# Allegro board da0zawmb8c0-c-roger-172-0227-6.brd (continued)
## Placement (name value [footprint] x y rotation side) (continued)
R14  100_1%_2  [R0201]  105.47 71.87 90 top
R15  *51_5%_2  [R0201]  103.82 75.49 180 top
R16  49.9_1%_2  [R0201]  77.91 46.85 180 top
R17  *51_5%_2  [R0201]  103.59 70.12 180 top
R18  49.9_1%_2  [R0201]  83.93 47.36 180 top
R19  51_5%_2  [R0201]  102.09 72.33 270 top
R20  49.9_1%_2  [R0201]  101.15 76.29 0 bottom
R21  49.9_1%_2  [R0201]  101.15 75.53 180 bottom
R22  100_1%_2  [R0201]  106.46 70.55 90 top
R23  1K_5%_2  [R0201]  105.6 71.66 0 bottom
R24  51_5%_2  [R0201]  102.22 73.95 180 top
R25  *51_5%_2  [R0201]  105.27 69.96 270 top
R26  470_1%_4  [R0402]  50.73 33.64 270 top
R27  *Short_0402  [S0402]  49.72 32.88 270 top
R28  121_1%_4  [R0402]  81.77 48.53 180 top
R29  80.6_1%_4  [R0402]  82.26 47.56 0 top
R30  100_1%_4  [R0402]  77.91 48.63 0 top
R31  *10K_5%_4  [R0402]  66.74 29.07 180 bottom
R32  *10K_5%_4  [R0402]  64.2 40.63 180 top
R33  8.2K_5%_4  [R0402]  59.62 51.17 270 top
R34  *1K_5%_4  [R0402]  102.3 60.18 0 bottom
R35  10K_5%_4  [R0402]  64.45 39.33 90 bottom
R36  10K_5%_4  [R0402]  60.77 51.93 90 top
R37  8.2K_5%_4  [R0402]  64.96 37.98 0 bottom
R38  100K_1%_4  [R0402]  60.64 52.18 90 bottom
R39  *0_5%_4  [R0402]  66.74 30.03 0 bottom
R40  100K_1%_4  [R0402]  64.96 35.75 0 bottom
R41  100K_1%_4  [R0402]  62.47 29.35 270 top
R42  1M_5%_2  [R0201]  48.96 26.02 180 top
R43  10K_1%_2  [R0201]  92.59 31.48 270 bottom
R44  4.7K_5%_2  [R0201]  81.19 44.69 270 top
R45  10K_5%_4  [R0402]  64.7 41.9 0 bottom
R46  10K_5%_4  [R0402]  65.34 44.69 90 top
R47  *Short_0402  [S0402]  62.93 43.8 0 top
R51  *0_5%_4  [R0402]  64.32 44.69 90 top
R52  1K_5%_2  [R0201]  103.06 54.15 90 bottom
R54  60.4_1%_2  [R0201]  101.13 54.32 90 bottom
R56  100K_1%_4  [R0402]  64.58 50.89 180 bottom
R59  *10K_5%_4  [R0402]  63.69 27.67 180 top
R60  10K_5%_4  [R0402]  96.79 25.36 90 bottom
R63  56.2_1%_4  [R0402]  105.6 69.73 180 bottom
R64  220_1%_4  [R0402]  103.57 69.79 180 bottom
R65  *54.9/F_4  [R0402]  105.6 70.7 0 bottom
R66  *0_4/S  [S0402]  101.38 68.79 270 bottom
R67  100_1%_4  [R0402]  103.57 71.28 0 bottom
R68  *0_4/S  [S0402]  101.79 70.22 180 bottom
R69  *Short_0402  [S0402]  101.53 56.4 90 bottom
R70  *Short_0603  [S0603]  109.23 44.18 90 top
R71  *Short_0603  [S0603]  63.43 54.22 180 top
R72  100_1%_2  [R0201]  80.43 47.43 90 top
R73  HDMI_N@10K_5%_4  [R0402]  66.74 31 0 bottom
R74  100_1%_2  [R0201]  79.46 47.43 90 top
R77  *Short_0805  [S0805]  88.67 60.88 270 top
R78  *Short_0805  [S0805]  86.69 60.88 270 top
R79  *0.0002_5%_0805  [R0805]  84.57 66.75 90 top
R80  *Short_0805  [S0805]  84.72 60.88 270 top
R81  *0.0002_5%_0805  [R0805]  86.54 66.75 90 top
R82  49.9_1%_2  [R0201]  104.38 68.44 270 top
R83  *1K_5%_2  [R0201]  105.47 73.37 180 bottom
R84  *Short_0402  [S0402]  66.74 43.42 180 bottom
R85  *0_5%_4  [R0402]  101.03 77.2 0 bottom
R86  *1K_5%_2  [R0201]  101.15 73.65 0 bottom
R87  1K_5%_2  [R0201]  101.15 74.66 0 bottom
R88  *100K_1%_4  [R0402]  66.74 33.21 0 bottom
R89  4.7K_5%_2  [R0201]  64.96 37.02 180 bottom
R90  *20K_1%_2  [R0201]  66.74 37.37 180 bottom
R91  22_1%_4  [R0402]  62.93 52.06 0 bottom
R92  22_1%_4  [R0402]  65.97 46.09 0 top
R94  10K_1%_2  [R0201]  82.61 28.31 270 top
R95  2.2K_5%_2  [R0201]  97.31 28.82 0 top
R96  8.2K_5%_4  [R0402]  81.09 25.01 90 top
R97  2.2K_5%_2  [R0201]  95.82 28.85 180 top
R98  *10K_1%_2  [R0201]  82.74 27.93 180 bottom
R99  2.2K_5%_2  [R0201]  93.03 28 270 top
R100  10K_5%_4  [R0402]  81.09 27.04 90 top
R101  2.2K_5%_2  [R0201]  92.06 28 270 top
R102  10K_1%_2  [R0201]  82.74 28.69 180 bottom
R103  2.2K_5%_2  [R0201]  89.72 31.61 180 bottom
R104  2.2K_5%_2  [R0201]  88.71 31.61 0 bottom
R106  33.2_1%_4  [R0402]  161.68 27.7 90 top
R107  100K_1%_4  [R0402]  162.01 33.08 0 top
R108  33.2_1%_4  [R0402]  160.72 27.7 90 top
R109  33.2_1%_4  [R0402]  161.99 31.61 0 top
R110  33.2_1%_4  [R0402]  159.75 27.7 90 top
R111  33.2_1%_4  [R0402]  160.46 31.41 90 top
R112  100K_1%_4  [R0402]  158.43 30.72 270 top
R113  33.2_1%_4  [R0402]  159.45 31.41 90 top
R114  4.7K_5%_2  [R0201]  69.63 16.71 270 top
R115  4.7K_5%_2  [R0201]  67.24 19.29 0 top
R116  *20K_1%_2  [R0201]  66.74 36.28 180 bottom
R117  *4.7K_5%_2  [R0201]  61.94 47.87 180 top
R118  1K_5%_2  [R0201]  62.6 46.6 90 top
R119  4.7K_5%_2  [R0201]  89.04 27.65 270 bottom
R120  *4.7K_5%_2  [R0201]  77.66 22.85 0 top
R121  *20K_1%_2  [R0201]  88.83 28.87 0 bottom
R122  10K_5%_4  [R0402]  76.31 23.51 270 top
R123  *10K_5%_4  [R0402]  90.87 27.93 90 top
R124  *20K_1%_2  [R0201]  65.97 40.47 180 top
R125  20K_1%_2  [R0201]  88.94 34.5 135 top
R134  10K_5%_4  [R0402]  93.38 26.28 90 bottom
R136  113_1%_4  [R0402]  95.44 40.63 180 top
R137  1K_5%_2  [R0201]  96.79 37.4 0 top
R138  1K_5%_2  [R0201]  96.58 39.33 0 top
R139  100_1%_2  [R0201]  95.92 38.37 180 top
R144  4.7K_5%_2  [R0201]  78.04 27.67 270 bottom
R145  60.4_1%_2  [R0201]  101.66 30.59 0 bottom
R146  150_1%_2  [R0201]  75.32 22.77 90 top
R147  200_1%_2  [R0201]  90.28 35.98 90 top
R148  10K_5%_4  [R0402]  97.22 35.42 90 top
R152  100K_5%_4  [R0402]  65.44 39.33 90 bottom
R153  *100K_5%_4  [R0402]  98.82 28.43 90 top
R154  10K_5%_4  [R0402]  65.97 34.68 0 top
R155  10K_5%_4  [R0402]  65.97 36.61 0 top
R157  *20K_1%_2  [R0201]  67.14 38.7 180 bottom
R158  100K_5%_4  [R0402]  97.85 30.26 270 top
R159  10K_5%_4  [R0402]  65.97 37.58 0 top
R161  *0_5%_4  [R0402]  79.44 27.67 90 bottom
R166  33.2_1%_4  [R0402]  98.87 31.1 90 bottom
R167  1M_5%_4  [R0402]  99.38 29.75 180 bottom
R168  33.2_1%_4  [R0402]  99.83 31.1 90 bottom
R169  10M_5%_4  [R0402]  77.91 31.36 180 bottom
R179  10K_5%_4  [R0402]  78.24 25.39 90 top
R180  20K_1%_2  [R0201]  194.14 23.61 180 bottom
R183  *4.7K_5%_2  [R0201]  106.41 32.65 90 top
R186  *1K_5%_2  [R0201]  61.66 48.88 90 bottom
R187  33_5%_2  [R0201]  62.93 46.09 0 bottom
R188  33_5%_2  [R0201]  61.28 49.01 0 top
R191  33_5%_2  [R0201]  62.93 45.12 0 bottom
R194  33_5%_2  [R0201]  62.82 50.53 180 top
R202  20K_1%_2  [R0201]  95.82 25.64 270 bottom
R209  200_1%_2  [R0201]  71.05 33.01 180 bottom
R210  *Short_0402  [S0402]  66.61 24.88 90 top
R211  *Short_0402  [S0402]  82.31 30.52 180 bottom
R212  *0_5%_4  [R0402]  89.52 27.52 0 top
R213  *Short_0402  [S0402]  89.8 30.24 0 top
R215  *100K_5%_4  [R0402]  60.16 24.4 270 bottom
R216  *1K_5%_2  [R0201]  105.73 68.97 180 top
R217  *1K_5%_2  [R0201]  101.13 75.07 90 top
R218  1K_5%_2  [R0201]  105.7 67.97 180 top
R220  *1K_5%_2  [R0201]  113.6 20.69 90 top
R221  *1K_5%_2  [R0201]  114.06 22.9 0 top
R222  *1.5K_5%_4  [R0402]  114.06 23.91 0 top
R224  240_1%_2  [R0201]  49.85 62.47 90 top
R225  *0_5%_4  [R0402]  48.32 34.28 180 top
R226  *0_5%_4  [R0402]  46.8 31.1 180 top
R227  *0_5%_4  [R0402]  50.48 54.6 180 top
R228  *Short_0402  [S0402]  48.32 33.26 0 top
R229  *Short_0402  [S0402]  47.48 32.09 0 top
R230  *Short_0402  [S0402]  52.26 54.34 180 top
R231  240_1%_2  [R0201]  61.63 72.12 0 bottom
R232  240_1%_2  [R0201]  61.63 73.14 0 bottom
R233  240_1%_2  [R0201]  50.23 73.52 180 top
R234  240_1%_2  [R0201]  61.63 74.15 180 bottom
R235  240_1%_2  [R0201]  61.63 71.11 180 bottom
R236  240_1%_2  [R0201]  61.63 70.09 180 bottom
R237  240_1%_2  [R0201]  50.23 74.54 180 top
R238  240_1%_2  [R0201]  61.63 75.17 180 bottom
R239  240_1%_2  [R0201]  50.23 71.49 180 top
R240  240_1%_2  [R0201]  50.23 70.47 180 top
R241  1K_1%_4  [R0402]  50.35 50.41 0 top
R242  2_1%_6  [R0603]  50.1 48.6 270 top
R243  1K_1%_4  [R0402]  50.35 51.42 180 top
R244  24.9_1%_4  [R0402]  49.85 46.34 90 top
R245  *Short_0402  [S0402]  41.46 34.91 180 top
R246  *Short_0402  [S0402]  42.61 48.12 0 top
R247  *Short_0402  [S0402]  43.62 69.46 0 top
R248  *Short_0402  [S0402]  44.89 82.79 0 top
R252  *0_5%_4  [R0402]  30.16 40.5 180 top
R253  240_1%_4  [R0402]  39.69 34.91 0 top
R254  240_1%_4  [R0402]  40.83 48.12 0 top
R255  240_1%_4  [R0402]  41.84 69.46 0 top
R256  240_1%_4  [R0402]  42.99 82.79 0 top
R257  *Short_0402  [S0402]  30.16 39.33 180 top
R261  1.8K_1%_4  [R0402]  44.61 96.51 270 top
R262  2.7_5%_6  [R0603]  51.37 98.89 0 top
R263  *0_5%_4  [R0402]  49.46 99.3 90 top
R264  1.8K_1%_4  [R0402]  47.43 98.54 90 top
R265  33_5%_4  [R0402]  29.27 88.43 0 top
R266  33_5%_4  [R0402]  29.27 87.46 0 top
R267  24.9_1%_4  [R0402]  55.43 99.17 180 top
R268  36_1%_4  [R0402]  37.32 96.63 90 top
R269  36_1%_4  [R0402]  29.27 84.57 180 top
R270  36_1%_4  [R0402]  38.29 96.63 90 top
R271  51_1%_4  [R0402]  32.32 82.79 0 top
R272  36_1%_4  [R0402]  42.15 96.63 90 top
R273  36_1%_4  [R0402]  40.22 96.63 90 top
R274  36_1%_4  [R0402]  30.29 95.24 180 top
R275  36_1%_4  [R0402]  30.29 92.34 180 top
R276  36_1%_4  [R0402]  29.6 96.63 90 top
R277  36_1%_4  [R0402]  30.29 93.31 180 top
R278  36_1%_4  [R0402]  30.29 90.41 180 top
R279  36_1%_4  [R0402]  30.29 94.27 180 top
R280  36_1%_4  [R0402]  34.43 96.63 90 top
R281  36_1%_4  [R0402]  29.27 86.5 180 top
R282  36_1%_4  [R0402]  33.46 96.63 90 top
R283  36_1%_4  [R0402]  30.29 91.38 180 top
R284  36_1%_4  [R0402]  39.25 96.63 90 top
R285  36_1%_4  [R0402]  31.53 96.63 90 top
R286  36_1%_4  [R0402]  35.39 96.63 90 top
R287  36_1%_4  [R0402]  30.29 89.44 180 top
R288  36_1%_4  [R0402]  36.36 96.63 90 top
R289  36_1%_4  [R0402]  29.27 85.53 180 top
R290  36_1%_4  [R0402]  32.5 96.63 90 top
R291  36_1%_4  [R0402]  41.18 96.63 90 top
R292  36_1%_4  [R0402]  43.11 96.63 90 top
R293  36_1%_4  [R0402]  30.57 96.63 90 top
R294  *36_1%_4  [R0402]  30.16 41.64 0 top
R296  *short_4  [S0402]  102.42 125.34 0 bottom
R297  EV@10K_1%_4  [R0402]  85.13 95.77 270 bottom
R299  *EV@Short_0402  [S0402]  101.28 109.33 180 top
R305  *EV@Short_0402  [S0402]  100.26 123.3 0 bottom
R306  EV@100K_1%_4  [R0402]  100.26 124.32 180 bottom
R307  *EV@200_1%_2  [R0201]  115.25 117.84 180 bottom
R311  EV@10K_1%_4  [R0402]  103.34 117.82 180 bottom
R312  EV@2.49K_1%_4  [R0402]  116.65 118.22 90 bottom
R313  EV@10K_1%_4  [R0402]  90.49 98.16 0 bottom
R314  EV@10K_1%_4  [R0402]  119.19 100.44 270 bottom
R315  EV@10K_1%_4  [R0402]  119.57 99.05 0 bottom
R316  EV@10K_1%_4  [R0402]  120.33 98.03 0 bottom
R317  EV@10K_1%_4  [R0402]  120.2 104.63 0 top
R318  EV@40.2_1%_4  [R0402]  120.2 93.08 0 top
R319  EV@40.2_1%_4  [R0402]  120.2 94.09 0 top
R320  EV@60.4_1%_2  [R0201]  120.48 94.09 0 bottom
R321  *EV@60.4_1%_2  [R0201]  110.43 97.11 0 top
R322  *EV@60.4_1%_2  [R0201]  110.76 100.01 270 top
R323  *EV@0_5%_4  [R0402]  100.77 118.22 180 bottom
R324  *EV@Short_0402  [S0402]  100.77 119.24 180 bottom
R325  EV@100K_1%_4  [R0402]  102.75 123.81 90 bottom
R326  EV@10K_5%_4  [R0402]  91.6 89.01 90 bottom
R329  *EV@Short_0402  [S0402]  98.63 102.8 90 top
R330  *EV@10K_1%_4  [R0402]  97.39 89.01 90 bottom
R331  EV@10K_1%_4  [R0402]  97.85 87.36 0 bottom
R332  EV@10K_1%_4  [R0402]  98.36 89.01 90 bottom
R339  *EV@Short_0402  [S0402]  108.98 88.81 180 bottom
R340  10K_1%_2  [R0201]  201.86 15.78 0 top
R341  EV@100K_5%_4  [R0402]  105.47 88.81 180 bottom
R342  EV@100K_5%_4  [R0402]  103.69 88.81 0 bottom
R343  EV@100K_5%_4  [R0402]  107.25 88.81 180 bottom
R344  EV@100K_5%_4  [R0402]  88.2 96.63 0 bottom
R345  EV@100K_5%_4  [R0402]  88.2 95.62 0 bottom
R346  EV@100K_5%_4  [R0402]  88.2 93.59 0 bottom
R347  *EV@100K_5%_4  [R0402]  88.2 97.65 0 bottom
R348  *EV@100K_5%_4  [R0402]  88.2 92.57 0 bottom
R349  *EV@100K_5%_4  [R0402]  88.2 94.6 0 bottom
R350  *EV@30.1K_1%_4  [R0402]  105.47 89.78 0 bottom
R351  *EV@100K_5%_4  [R0402]  107.25 89.78 180 bottom
R352  EV@100K_5%_4  [R0402]  103.69 89.78 180 bottom
R353  EV@100K_5%_4  [R0402]  90.49 96.13 180 bottom
R354  EV@100K_5%_4  [R0402]  90.49 94.98 0 bottom
R355  EV@100K_5%_4  [R0402]  90.49 92.95 180 bottom
R356  EV@100K_5%_4  [R0402]  90.49 97.14 180 bottom
R357  EV@100K_5%_4  [R0402]  90.49 91.93 180 bottom
R358  EV@100K_5%_4  [R0402]  90.49 93.97 180 bottom
R359  *0_5%_4  [R0402]  179.08 31.91 90 top
R361  4.7K_5%_2  [R0201]  192.82 32.24 90 top
R362  EV@4.7K_5%_2  [R0201]  171.36 30.19 0 top
R363  EV@2.2K_5%_2  [R0201]  96.43 89.01 270 bottom
R364  *EV@Short_0402  [S0402]  96.12 87.36 0 bottom
R365  EV@4.7K_5%_2  [R0201]  173.11 30.19 180 top
R366  EV@2.2K_5%_2  [R0201]  95.46 89.01 270 bottom
R367  EV@2.2K_5%_2  [R0201]  94.5 89.01 270 bottom
R368  EV@2.2K_5%_2  [R0201]  93.53 89.01 270 bottom
R369  4.7K_5%_2  [R0201]  192.11 32.24 90 top
R370  *EV@Short_0402  [S0402]  90.23 89.95 180 bottom
R372  *EV@Short_0402  [S0402]  90.18 95.01 270 top
R373  *EV@Short_0402  [S0402]  89.85 98.67 180 top
R374  *EV@Short_0402  [S0402]  87.95 97.01 180 top
R376  *EV@Short_0402  [S0402]  90.23 90.92 180 bottom
R378  *EV@10K_1%_4  [R0402]  202.37 12.94 180 top
R380  43_5%_4  [R0402]  179.08 30.19 270 top
R382  *EV@0_5%_4  [R0402]  100.52 124.07 180 top
R383  4.7K_5%_2  [R0201]  190.69 32.27 90 top
R384  *EV@Short_0402  [S0402]  102.3 124.07 180 top
R385  *EV@4.7K_5%_2  [R0201]  100.52 123.05 0 top
R386  EV@10K_5%_4  [R0402]  85.79 94.73 270 top
R391  EV@10K_1%_4  [R0402]  87.95 90.56 0 bottom
R394  EV@10K_1%_4  [R0402]  90.18 93.1 90 top
R395  EV@10K_1%_4  [R0402]  90.23 88.99 0 bottom
R396  EV@10K_1%_4  [R0402]  95.06 119.24 180 bottom
R397  EV@10K_1%_4  [R0402]  87.95 98.03 0 top
R398  EV@100K_1%_4  [R0402]  98.74 96.63 90 top
R399  *EV@10K_1%_4  [R0402]  88.2 89.52 0 bottom
R402  *22_5%_4  [R0402]  179.87 23.23 180 top
R403  EV@10K_1%_4  [R0402]  85.41 97.01 0 top
R404  EV@10K_1%_4  [R0402]  88.2 91.55 0 bottom
R405  EV@120_1%_4  [R0402]  132.78 97.65 90 bottom
R406  EV@120_1%_4  [R0402]  132.4 102.35 180 bottom
R407  EV@549_1%_4  [R0402]  133.92 100.06 0 top
R409  100K_1%_4  [R0402]  53.78 26.4 90 top
R410  EV@1.33K_1%_4  [R0402]  133.92 99.05 0 top
R411  EV@931_1%_4  [R0402]  133.92 101.08 0 top
R414  TPC@20K_1%_2  [R0201]  16.7 47.23 90 top
R415  TPC@39K_1%_4  [R0402]  16.7 49.01 90 top
R416  TPC@100K_5%_4  [R0402]  23.56 47.36 90 top
R417  TPC@10K_5%_4  [R0402]  23.94 49.9 0 top
R418  TPC@10K_5%_4  [R0402]  23.94 48.88 0 top
R421  *Short_0402  [S0402]  22.69 53.45 180 top
R422  *Short_0402  [S0402]  22.69 54.47 180 top
R423  *Short_0402  [S0402]  23.94 58.66 180 top
R424  *Short_0402  [S0402]  23.94 57.64 180 top
R425  *Short_0402  [S0402]  22.16 34.15 180 top
R426  *Short_0402  [S0402]  22.16 35.17 180 top
R427  *Short_0402  [S0402]  22.16 32.12 180 top
R428  *Short_0402  [S0402]  22.16 33.13 180 top
R429  *Short_0402  [S0402]  22.67 36.94 180 top
R430  *Short_0402  [S0402]  22.67 37.96 180 top
R436  *short_4  [S0402]  56.45 104.89 180 top
R439  *1K_5%_2  [R0201]  52.36 107.3 270 top
R440  *1K_5%_2  [R0201]  59.02 110.73 270 top
R441  1K_1%_4  [R0402]  54.29 107.3 90 top
R442  100K_1%_4  [R0402]  55.26 107.3 270 top
R443  10_5%_4  [R0402]  53.33 107.3 270 top
R445  *short_4  [S0402]  82.61 96.02 180 bottom
R446  100K_1%_4  [R0402]  80.83 96.02 180 bottom
R447  100K_5%_4  [R0402]  203.16 38.37 90 bottom
R448  256@0_5%_4  [R0402]  213.12 32.29 0 top
R449  255@0_5%_4  [R0402]  211.72 36.18 90 bottom
R450  *short_6  [S0603]  198.49 34.73 0 bottom
R451  200K_1%_4  [R0402]  199.43 30.72 0 bottom
R452  255@100K_5%_4  [R0402]  200.59 29.04 90 bottom
R453  *256@0_5%_4  [R0402]  208.67 30.24 90 top
R454  *255@0_5%_4  [R0402]  209.31 28.21 270 top
R455  *Short_0603  [S0603]  211.15 25.34 0 bottom
R459  *Short_0402  [S0402]  208.01 28.13 90 bottom
R460  *short_4  [S0402]  204.84 27.52 90 top
R461  22_5%_2  [R0201]  206.74 27.57 90 bottom
R462  *0_5%_4  [R0402]  202.63 27.52 90 top
R463  *short_4  [S0402]  210.63 37.83 180 top
R464  *0_5%_4  [R0402]  210.75 35.8 180 top
R465  *0_5%_4  [R0402]  198.03 29.7 90 bottom
R467  *0_5%_4  [R0402]  198.77 35.95 0 bottom
R468  2.2K_5%_2  [R0201]  213.57 42.91 0 top
R469  *0_5%_4  [R0402]  210.63 38.85 180 top
R470  *short_4  [S0402]  202.02 29.83 135 top
R471  2.2K_5%_2  [R0201]  213.57 43.93 0 top
R472  62_1%_4  [R0402]  213.55 46.62 0 top
R473  62_1%_4  [R0402]  213.55 47.66 0 top
R474  *10K_5%_4  [R0402]  215.38 45.22 180 top
R475  *10K_5%_4  [R0402]  214.82 49.01 180 top
R476  4.7K_5%_2  [R0201]  213.57 45.27 90 top
R477  4.7K_5%_2  [R0201]  213.09 48.63 0 top
R478  1K_5%_2  [R0201]  210.65 28.28 0 top
R479  *10K_5%_4  [R0402]  210.65 29.3 180 top
R480  *Short_0603  [S0603]  118.86 17.97 270 top
R481  *Short_0603  [S0603]  117.44 17.97 270 top
R482  *Short_0603  [S0603]  116.01 17.97 270 top
R483  *Short_0603  [S0603]  114.54 17.97 270 top
R484  *150_1%_4  [R0402]  14.16 78.73 90 bottom
R486  *150_1%_4  [R0402]  14.16 76.82 90 bottom
R487  *150_1%_4  [R0402]  14.16 74.92 90 bottom
R489  *150_1%_4  [R0402]  14.16 80.76 90 bottom
R490  2.2K_5%_2  [R0201]  20.25 74.15 90 top
R491  2.2K_5%_2  [R0201]  22.24 73.65 90 top
R494  2.2K_5%_2  [R0201]  18.73 83.64 270 top
R495  *HDD_R@4.7K_5%_2  [R0201]  204.53 14.74 180 top
R497  HDD_R@4.7K_5%_2  [R0201]  206.82 13.32 0 top
R498  *HDD_R@4.7K_5%_2  [R0201]  204.53 13.78 180 top
R499  *HDD_R@4.7K_5%_2  [R0201]  206.82 12.56 0 top
R500  HDD_R@4.7K_5%_2  [R0201]  204.53 12.81 180 top
R502  2.2K_5%_2  [R0201]  19.75 83.64 270 top
R503  *HDD_R@4.7K_5%_2  [R0201]  204.53 15.71 180 top
R504  HDD_R@4.7K_5%_2  [R0201]  206.82 16.75 0 top
R505  *HDD_R@4.7K_5%_2  [R0201]  204.53 16.67 180 top
R506  *HDD_R@4.7K_5%_2  [R0201]  206.82 18.91 0 top
R507  HDMI_R@12.4K_1%_4  [R0402]  20.89 83.81 270 top
R508  2.49K_1%_4  [R0402]  42.18 112.36 90 top
R509  1K_5%_2  [R0201]  51.37 104.51 0 top
R510  15K_1%_4  [R0402]  49.59 104.61 0 top
R511  10_5%_4  [R0402]  45.78 109.84 90 top
R512  680_5%_4  [R0402]  44.77 109.84 270 top
R513  *short_4  [S0402]  49.59 105.57 0 top
R516  75_1%_8  [R0805]  37.53 111.37 90 top
R517  75_1%_8  [R0805]  34.73 111.37 90 top
R518  75_1%_8  [R0805]  31.68 111.62 90 top
R519  75_1%_8  [R0805]  28.76 111.52 90 top
R551  *10K_1%_2  [R0201]  94.22 25.87 270 bottom
R554  *10K_5%_4  [R0402]  93.86 29.81 270 bottom
R557  *0_5%_4  [R0402]  75.93 17.64 270 top
R558  *Short_0402  [S0402]  74.97 17.64 90 top
R559  4.7K_5%_2  [R0201]  69.18 21.32 270 top
R560  *Short_0402  [S0402]  70.65 19.44 180 top
R561  *0_5%_4  [R0402]  70.65 18.48 0 top
R562  4.7K_5%_2  [R0201]  73.34 18.4 0 top
R563  *10K_5%_4  [R0402]  70.55 20.74 0 top
R565  *10K_5%_4  [R0402]  76.13 19.29 0 top
R566  4.7K_5%_2  [R0201]  68.21 21.37 90 top
R567  4.7K_5%_2  [R0201]  73.72 20.43 180 top
R572  *short_4  [S0402]  76.54 23.91 180 bottom
R573  *short_4  [S0402]  78.29 21.47 90 top
R574  *10K_5%_4  [R0402]  78.42 22.97 180 bottom
R575  *Short_0805  [S0805]  176.34 27.24 180 top
R576  1K_5%_2  [R0201]  172.88 28.51 180 top
R579  KBL@10K_5%_4  [R0402]  196.12 18.96 270 bottom
R580  TPM@10K_1%_2  [R0201]  121.47 24.34 0 top
R582  *GS@Short_0402  [S0402]  54.04 24.5 90 top
R583  TPM@10K_1%_2  [R0201]  121.42 17.66 0 top
R586  TPM@10K_1%_2  [R0201]  121.25 22.11 0 top
R589  *short_4  [S0402]  63.69 22.24 0 top
R590  *GS@Short_0201  [S0201]  63.31 19.72 180 top
R591  *GS@Short_0201  [S0201]  60.39 17.39 90 top
R592  *TPM@Short_0201  [S0201]  125.69 16.27 0 top
R593  *TPM@Short_0201  [S0201]  121.47 23.61 0 top
R596  TPM@33_5%_2  [R0201]  120.41 23.61 0 top
R597  TPM@33_5%_2  [R0201]  121.7 20.65 0 top
R598  TPM@33_5%_2  [R0201]  121.42 16.95 0 top
R599  *TPM@Short_0201  [S0201]  121.19 22.85 0 top
R600  *TPM@1.2K_5%_2  [R0201]  130.34 20.56 180 top
R601  *TPM@Short_0201  [S0201]  122.87 24.5 270 top
R604  *49.9K_1%_2  [R0201]  90.03 26 90 bottom
R605  *49.9K_1%_4  [R0402]  91.35 29.78 270 bottom
R606  *49.9K_1%_4  [R0402]  91.68 28.03 90 bottom
R607  *49.9K_1%_2  [R0201]  91.37 31.48 270 bottom
R608  *PBA@0_5%_4  [R0402]  47.81 18.4 90 top
R609  PBA@10K_5%_4  [R0402]  52.64 18.27 270 top
R614  *short_4  [S0402]  55.31 21.83 180 bottom
R638  ODD@10K_5%_4  [R0402]  127.05 16.29 0 top
R639  *ODD@Short_0805  [S0805]  123.3 20.05 180 bottom
R640  ODD@33_5%_2  [R0201]  140.52 19.93 270 bottom
R641  *ODD@10K_5%_4  [R0402]  139.51 20.69 270 bottom
R645  *SSD@Short_0201  [S0201]  31.43 3.54 0 top
R646  *SSD@Short_0201  [S0201]  29.14 11.54 270 bottom
R647  *SSD@Short_0201  [S0201]  29.91 11.54 270 bottom
R648  *SSD@Short_0201  [S0201]  28.76 3.54 0 top
R649  SSD@100K_1%_4  [R0402]  22.29 8.24 180 top
R651  4.7K_5%_2  [R0201]  180.2 14.97 270 bottom
R652  4.7K_5%_2  [R0201]  181.37 19.85 270 bottom
R653  *SSD@Short_0201  [S0201]  26.73 6.59 180 top
R654  *SSD@0_5%_2  [R0201]  22.29 9.26 0 top
R655  *0_5%_4  [R0402]  195.06 17.89 270 bottom
R662  CNV@20K_1%_2  [R0201]  104.46 32.12 90 top
R663  CNV@20K_1%_2  [R0201]  105.22 32.12 90 top
R664  CNV@20K_1%_2  [R0201]  196.86 22.97 0 bottom
R665  CNV@22_1%_4  [R0402]  196.3 26.73 180 bottom
R666  CNV@33_5%_2  [R0201]  104.56 33.18 270 top
R667  CNV@22_1%_4  [R0402]  193.15 23.33 270 bottom
R668  CNV@33_5%_2  [R0201]  103.85 33.18 270 top
R670  *Short_0402  [S0402]  193.53 21.42 180 bottom
R671  *10K_1%_2  [R0201]  192.72 18.88 0 bottom
R672  *10K_1%_2  [R0201]  193.48 18.15 0 bottom
R673  *Debug@Short_0201  [S0201]  193.08 17.39 0 bottom
R674  *Debug@Short_0201  [S0201]  193.48 15.1 0 bottom
R675  *Debug@Short_0201  [S0201]  193.48 14.34 0 bottom
R676  CNV@75K_1%_4  [R0402]  146.87 29.7 180 top
R677  CNV@75K_1%_4  [R0402]  147.03 24.93 180 top
R678  CNV@75K_1%_4  [R0402]  147.84 23.63 0 top
R679  CNV@71.5K_1%_4  [R0402]  145.6 18.2 180 top
R696  *HDMI_R@Short_0201  [S0201]  15.56 74.26 180 top
R697  *HDMI_R@Short_0201  [S0201]  15.56 75.45 180 top
R698  *HDMI_R@Short_0201  [S0201]  15.56 76.16 180 top
R699  *HDMI_R@Short_0201  [S0201]  15.56 77.35 180 top
R700  *HDMI_R@Short_0201  [S0201]  15.56 78.07 180 top
R701  *HDMI_R@Short_0201  [S0201]  15.56 79.26 180 top
R702  *HDMI_R@Short_0201  [S0201]  15.56 79.97 180 top
R703  *HDMI_R@Short_0201  [S0201]  15.56 81.16 180 top
R706  HDMI_N@470_1%_4  [R0402]  13.78 81.39 0 top
R707  HDMI_N@470_1%_4  [R0402]  13.78 80.38 0 top
R708  HDMI_N@470_1%_4  [R0402]  13.78 79.36 0 top
R709  HDMI_N@470_1%_4  [R0402]  13.78 78.35 0 top
R710  HDMI_N@470_1%_4  [R0402]  13.78 77.33 0 top
R711  HDMI_N@470_1%_4  [R0402]  13.78 76.31 0 top
R712  HDMI_N@470_1%_4  [R0402]  13.78 75.3 0 top
R713  HDMI_N@470_1%_4  [R0402]  13.78 74.28 0 top
R720  33_5%_2  [R0201]  148.88 19.95 90 top
R732  *100K_5%_4  [R0402]  205.78 27.55 90 bottom
R733  256@100K_5%_4  [R0402]  200.16 29.4 180 top
R734  10K_1%_2  [R0201]  195.87 30.01 90 bottom
R735  *Short_0201  [S0201]  196.02 34.02 0 bottom
R736  255@0_5%_4  [R0402]  196.3 35.01 0 bottom
R737  256@0_5%_4  [R0402]  197.04 35.98 0 bottom
R738  255@0_5%_4  [R0402]  198.64 24.73 90 bottom
R739  256@0_5%_4  [R0402]  201.26 27.27 90 bottom
R740  256@0_5%_4  [R0402]  198.74 28.08 0 bottom
R741  256@3.3K_5%_2  [R0201]  198.64 26.1 180 bottom
R742  256@3.3K_5%_2  [R0201]  198.44 27.16 180 bottom
R746  *10K_5%_4  [R0402]  17.71 83.81 270 top
R747  10K_5%_4  [R0402]  23.05 84.31 90 top
R748  *0_5%_4  [R0402]  21.91 83.81 270 top
R749  0_5%_4  [R0402]  16.7 83.81 270 top
R750  *Short_0402  [S0402]  20 85.33 0 top
R775  *short_4  [S0402]  25.97 62.72 90 top
R777  *short_4  [S0402]  25.97 64.5 270 top
R821  1K/F_4  [R0402]  140.9 35.67 0 top
R822  1K/F_4  [R0402]  143.17 33.74 90 top
R825  *100K_1%_4  [R0402]  138.24 33.59 180 top
R890  100K_5%_2  [R0201]  180 16.42 270 top
R894  *Short_0201  [S0201]  179.21 18.27 0 top
R895  33_5%_2  [R0201]  196.25 32.24 90 top
R951  45.3K_1%_4  [R0402]  44.64 23.35 0 top
R953  1K/F_4  [R0402]  47.18 23 270 top
R956  33_5%_2  [R0201]  203.03 22.69 270 top
R960  33_5%_2  [R0201]  203.82 23.91 0 top
R971  20K_1%_2  [R0201]  48.96 27.04 0 top
R978  1.5K_5%_4  [R0402]  46.04 22.97 270 top
R979  20K_1%_2  [R0201]  48.96 25.01 0 top
R1234  HDD_R@4.7K_5%_2  [R0201]  206.82 14.72 0 top
R1235  HDD_R@4.7K_5%_2  [R0201]  206.82 15.61 0 top
R1236  *HDD_R@4.7K_5%_2  [R0201]  206.82 17.77 0 top
R1237  HDD_R@4.7K_5%_2  [R0201]  205.04 18.91 180 top
R1238  HDD_R@4.7K_5%_2  [R0201]  204.53 17.64 180 top
R1239  *HDD_R@Short_0402  [S0402]  204.91 11.16 90 top
R1250  20K_1%_2  [R0201]  15.09 86.98 0 top
R1251  *Short_0805  [S0805]  86.45 26.68 270 bottom
R1252  *20K_1%_2  [R0201]  80.83 27.42 270 bottom
R1253  *Short_0603  [S0603]  96.96 30.31 0 bottom
R1260  *Short_0402  [S0402]  100.01 35.04 180 top
R1262  *Short_0402  [S0402]  101.1 40.83 180 bottom
R1264  *Short_0402  [S0402]  101.38 39.86 180 bottom
R1265  *Short_0402  [S0402]  102.55 44.18 0 top
R1266  *Short_0402  [S0402]  102.55 42.25 0 top
R1267  *Short_0402  [S0402]  100.26 28.43 180 top
R1270  *Short_0402  [S0402]  86.04 31.1 90 top
R1271  *Short_0402  [S0402]  102.55 43.22 0 top
R1272  *Short_0603  [S0603]  96.96 28.74 180 bottom
R1273  *Short_0402  [S0402]  87.44 30.09 180 bottom
R1274  *Short_0402  [S0402]  87.44 28.79 180 bottom
R1275  *Short_0805  [S0805]  102.09 38.39 0 bottom
R1276  *Short_0402  [S0402]  87.06 31.1 270 top
R1277  *Short_0603  [S0603]  104.84 29.2 0 bottom
R1278  *Short_0402  [S0402]  88.83 32.56 0 top
R1279  *Short_0402  [S0402]  103.21 35.98 270 top
R1280  *Short_0402  [S0402]  100.65 44.49 0 top
R1281  *Short_0402  [S0402]  85.02 31.1 270 top
R1284  HDMI_N@0_5%_2  [R0201]  26.22 74.92 0 top
R1285  HDMI_N@0_5%_2  [R0201]  26.22 76.06 0 top
R1286  HDMI_N@0_5%_2  [R0201]  26.22 76.82 0 top
R1287  HDMI_N@0_5%_2  [R0201]  26.22 77.96 0 top
R1288  HDMI_N@0_5%_2  [R0201]  26.22 78.73 0 top
R1289  HDMI_N@0_5%_2  [R0201]  26.22 79.87 0 top
R1290  HDMI_N@0_5%_2  [R0201]  26.22 80.63 0 top
R1291  HDMI_N@0_5%_2  [R0201]  26.22 81.77 0 top
R2356  *Short_0201  [S0201]  200.77 21.96 0 top
R2525  *Short_0805  [S0805]  102.09 36.41 0 bottom
R2652  *SSD@Short_0201  [S0201]  39.05 11.54 270 bottom
R2653  *SSD@Short_0201  [S0201]  38.29 11.54 270 bottom
R2654  *SSD@Short_0201  [S0201]  35.75 11.54 270 bottom
R2655  *SSD@Short_0201  [S0201]  34.99 11.54 270 bottom
R2656  *SSD@Short_0201  [S0201]  32.95 11.54 270 bottom
R2657  *SSD@Short_0201  [S0201]  32.19 11.54 270 bottom
R2658  *SSD@Short_0201  [S0201]  27.75 11.54 270 bottom
R2659  *SSD@Short_0201  [S0201]  26.99 11.54 270 bottom
R2660  *SSD@100K_5%_4  [R0402]  31.43 2.65 180 top
R2661  *SSD@Short_0805  [S0805]  24.95 3.03 180 top
R2662  *Debug@Short_0201  [S0201]  193.48 13.58 0 bottom
R2663  *Debug@Short_0201  [S0201]  179.64 24.09 90 bottom
R2664  *Debug@Short_0201  [S0201]  181.37 24.88 90 bottom
R2665  *Short_0201  [S0201]  178.32 18.6 270 top
R2666  *CNV_N@0_5%_8  [R0805]  193.89 28.87 180 bottom
R2667  *CNV@Short_0805  [S0805]  193.76 26.48 180 bottom
R6504  TPC@100K_1%_4  [R0402]  27.75 18.02 90 bottom
R6505  TPC@100K_1%_4  [R0402]  27.52 19.8 90 bottom
R6506  *TPC@100K_1%_4  [R0402]  26.55 19.8 90 bottom
R6508  TPC@100K_1%_4  [R0402]  22.16 19.01 180 bottom
R6510  TPC@100K_1%_4  [R0402]  21.7 17.72 180 bottom
R6515  TPC@100K_1%_4  [R0402]  25.97 11.9 270 bottom
R6516  TPC@100K_1%_4  [R0402]  24.95 11.9 270 bottom
R6517  TPC@100K_1%_4  [R0402]  23.28 12.13 90 bottom
R6603  TPC@10K_1%_4  [R0402]  21.32 17.69 270 top
R9041  *TPC@4.7K_5%_4  [R0402]  25.16 20.18 90 bottom
R9042  TPC@4.7K_5%_4  [R0402]  24.19 20.18 90 bottom
R9048  *TPC@Short_0603  [S0603]  20.99 26.05 90 bottom
R9261  *Short_0805  [S0805]  111.67 45.1 0 top
R10880  *10K_1%_2  [R0201]  95.06 26.4 270 bottom
R25270  *100K_1%_4  [R0402]  60.72 108.06 0 top
R25271  *100K_1%_4  [R0402]  60.72 109.33 0 top
R25272  *TPC@4.7K_5%_2  [R0201]  20.13 24.24 180 bottom
R25273  *TPC@4.7K_5%_2  [R0201]  16.95 18.66 180 bottom
R25274  *TPC@4.7K_5%_2  [R0201]  19.75 25.64 90 bottom
R25275  *TPC@4.7K_5%_2  [R0201]  16.34 25.79 270 bottom
R25276  *TPC@4.7K_5%_2  [R0201]  19.32 18.4 270 bottom
R25277  *TPC@4.7K_5%_2  [R0201]  20.33 18.4 90 bottom
R25278  TPC@4.7K_5%_2  [R0201]  15.58 25.26 90 bottom
R25279  *TPC@4.7K_5%_2  [R0201]  16.95 19.67 0 bottom
R25280  *short_4  [S0402]  19.75 19.8 0 bottom
R25282  EV@1.33K_1%_4  [R0402]  132.65 104.38 180 top
R25283  EV@931_1%_4  [R0402]  134.43 103.11 0 top
R25284  EV@549_1%_4  [R0402]  134.43 104.38 0 top
R25285  *Short_0805  [S0805]  67.55 107.05 90 bottom
R25288  *Short_0402  [S0402]  46.16 103.62 90 bottom
R25289  *Short_0402  [S0402]  47.18 103.62 90 bottom
R25290  *Short_0402  [S0402]  44.13 103.62 90 bottom
R25291  *Short_0402  [S0402]  45.15 103.62 90 bottom
R25292  *TPC@Short_0402  [S0402]  11.49 11.8 180 top
R25293  *TPC@Short_0402  [S0402]  11.49 10.78 180 top
R25294  HDMI_N@1M_5%_2  [R0201]  18.1 85.33 180 top
R25295  *Short_0402  [S0402]  47.69 21.32 180 top
R25296  *Short_0805  [S0805]  49.21 111.75 270 top
R25297  *Short_0402  [S0402]  14.92 84.95 0 top
R25298  100K_5%_4  [R0402]  177.48 19.14 90 top
R25300  100K_5%_4  [R0402]  177.05 22.08 90 top
R25303  *10K_1%_2  [R0201]  194.96 32.24 90 top
R25304  4.7K_5%_2  [R0201]  189.98 32.27 90 top
R25306  2.2_5%_6  [R0603]  175.22 23.23 0 top
R25307  *2.2_5%_6  [R0603]  179.44 26.81 180 top
R25308  33_5%_2  [R0201]  183.91 32.35 180 top
R25309  10K_1%_2  [R0201]  195.64 31.36 180 top
R25310  100K_5%_4  [R0402]  65.21 102.98 90 top
R25311  100K_5%_2  [R0201]  201.99 17.05 0 top
R25312  10K_5%_4  [R0402]  171.11 28.31 180 top
R25314  10K_1%_2  [R0201]  193.53 32.24 90 top
R25315  33_5%_2  [R0201]  180.43 27.88 180 top
R25316  *10K_1%_2  [R0201]  194.24 32.24 90 top
R25317  2.2_5%_6  [R0603]  177.96 25.39 180 top
R25318  33_5%_2  [R0201]  197.52 11.62 180 top
R25320  100K_5%_2  [R0201]  181.72 30.21 270 top
R25321  *Short_0402  [S0402]  19.62 57.26 180 bottom
R25322  EV@10K_1%_4  [R0402]  200.47 12.94 180 top
R25323  *10K_1%_2  [R0201]  182.79 32.35 0 top
R25328  33_5%_2  [R0201]  202.8 25.01 180 top
R25330  *short_4  [S0402]  180.48 30.14 0 top
R25332  *TPC@0_5%_6  [R0603]  12.58 19.59 0 bottom
R25336  *Short_0805  [S0805]  63.77 22.82 0 bottom
R25337  *short_4  [S0402]  13.02 4.3 0 top
R25338  TPC@100K_1%_4  [R0402]  18.98 8.62 180 top
R25339  TPC@10K_1%_4  [R0402]  14.79 10.43 0 top
R25340  TPC@422K_1%_4  [R0402]  15.4 13.83 90 top
R25341  TPC@100K_1%_4  [R0402]  17.33 12.1 0 top
R25342  TPC@470_1%_6  [R0603]  13.14 9.64 90 top
R25343  *Short_0603  [S0603]  114.11 22.85 180 bottom
R25344  *TPM@0_5%_6  [R0603]  132.27 19.54 180 top
R25346  *TPM@Short_0603  [S0603]  132.65 21.58 90 top
R25347  *TPM@0_5%_6  [R0603]  131.94 17.51 270 top
R25348  *TPM@Short_0603  [S0603]  134.25 17.51 270 top
R25350  HDD_N@0_5%_2  [R0201]  212.51 20.38 90 top
R25351  HDD_N@0_5%_2  [R0201]  211.14 20.38 90 top
R25352  HDD_N@0_5%_2  [R0201]  210.37 20.38 90 top
R25353  HDD_N@0_5%_2  [R0201]  209.1 20.38 90 top
R25355  *GS@10K_1%_2  [R0201]  63.31 21.2 180 top
R25356  *GS@10K_1%_2  [R0201]  58.23 17.39 0 top
R25357  *Short_0402  [S0402]  62.42 43.8 0 bottom
R25358  10K_1%_2  [R0201]  86.29 23.61 270 bottom
R25359  *0_5%_4  [R0402]  91.81 24.09 90 bottom
R25362  *Short_0402  [S0402]  92.77 24.09 90 bottom
R25363  TPC_N@0_5%_8  [R0805]  21.78 48.88 90 bottom
R25364  TPC_N@0_5%_8  [R0805]  18.53 48.88 90 bottom
R25365  *short_4  [S0402]  57.64 108.95 90 top
R25366  *short_4  [S0402]  57.72 107.17 270 top
R25367  10K_5%_4  [R0402]  57.85 110.73 270 top
R25368  10K_5%_4  [R0402]  52.92 108.95 180 top
R25369  100K_5%_4  [R0402]  58.99 108.95 180 top
R25370  *100K_5%_4  [R0402]  53.02 109.97 0 top
R25371  22K_5%_4  [R0402]  196.02 32.24 270 bottom
R25372  10K_5%_4  [R0402]  178.98 28.28 0 top
R25373  10K_5%_4  [R0402]  176.57 28.76 180 top
R25374  33_5%_2  [R0201]  59.88 46.6 0 top
R25375  EV@100K_1%_4  [R0402]  66.36 32.37 270 top
R25376  *EV@10K_1%_2  [R0201]  64.7 39.36 270 top
R25377  IV@1K/F_4  [R0402]  65.97 33.72 180 top
R25378  SP@10K_5%_4  [R0402]  85.25 31.1 90 bottom
R25379  SP@10K_5%_4  [R0402]  84.16 30.87 270 bottom
R25380  SP@10K_5%_4  [R0402]  84.16 23.96 0 bottom
R25381  SP@10K_5%_4  [R0402]  84.57 26.88 180 bottom
R25382  SP@10K_5%_4  [R0402]  83.88 28.69 90 bottom
R25383  SP@10K_5%_4  [R0402]  83.86 25.49 270 bottom
R25384  SP@10K_5%_4  [R0402]  80.43 25.28 0 bottom
R25385  SP@10K_5%_4  [R0402]  79.72 26.3 180 bottom
R25386  *10K_5%_4  [R0402]  66.74 31.96 0 bottom
R25387  10K_5%_4  [R0402]  65.09 32.47 90 bottom
R25388  DMIC@10K_5%_4  [R0402]  65.01 30.11 0 bottom
R25389  *10K_5%_4  [R0402]  65.01 31.08 0 bottom
R25390  TPC@10K_5%_4  [R0402]  64.96 34.78 0 bottom
R25391  TPC_N@10K_5%_4  [R0402]  66.74 35.32 0 bottom
R25392  10K_5%_4  [R0402]  66.74 34.17 0 bottom
R25393  GS_N@10K_5%_4  [R0402]  61.35 25.49 270 top
R25394  TPM_N@10K_5%_4  [R0402]  65.01 26.02 270 top
R25395  *10K_5%_4  [R0402]  64.96 33.82 0 bottom
R25396  HDMI_R@10K_5%_4  [R0402]  64.98 29.15 0 bottom
R25397  GS@10K_5%_4  [R0402]  62.8 25.26 180 top
R25398  10K_5%_4  [R0402]  61.53 27.67 180 top
R25399  TPM@10K_5%_4  [R0402]  62.93 26.28 0 top
R25403  EV@100K_5%_4  [R0402]  79.31 26.28 90 top
R25413  *2.2K_5%_2  [R0201]  94.8 25.64 0 top
R25415  *2.2K_5%_2  [R0201]  96.2 25.28 90 top
R25428  10K_5%_4  [R0402]  77.28 24.5 270 top
R25429  *EV@10K_5%_4  [R0402]  79.31 24.24 270 top
R25430  EV@10K_5%_4  [R0402]  77.07 25.01 0 bottom
R25431  *EV@10K_5%_4  [R0402]  76.9 27.67 90 bottom
R25433  *10K_1%_2  [R0201]  91.88 33.9 90 top
R25434  *10K_1%_2  [R0201]  93.91 31.48 270 bottom
R25436  20K_1%_2  [R0201]  101.51 25.16 0 bottom
R25437  10K_5%_4  [R0402]  94.68 35.04 180 top
R25438  10K_5%_4  [R0402]  94.93 36.82 180 top
R25439  10K_5%_4  [R0402]  100.39 31.23 180 top
R25440  *10K_5%_4  [R0402]  65.97 39.51 0 top
R25441  *10K_5%_4  [R0402]  65.97 38.54 0 top
R25444  *10K_5%_4  [R0402]  57.42 98.41 180 top
R25445  10K_5%_4  [R0402]  61.66 98.36 90 top
R25446  *0_5%_4  [R0402]  57.34 99.81 270 top
R25448  *Short_0402  [S0402]  99.6 25.16 180 bottom
R25449  *Short_0201  [S0201]  89.47 30.21 90 bottom
R25450  *Short_0201  [S0201]  88.71 30.21 90 bottom
R25456  *0_5%_6  [R0603]  62.37 104.81 180 top
R25458  *Short_0603  [S0603]  62.37 103.39 0 top
R25459  *Short_0603  [S0603]  59.12 104.76 270 bottom
R25462  *0_5%_6  [R0603]  60.26 102.91 270 top
R25465  *Short_0402  [S0402]  58.99 103.11 270 top
R25466  *Short_0603  [S0603]  98.84 25.01 180 top
R25467  33_5%_2  [R0201]  55.05 104.89 90 top
R25468  *EV@Short_0402  [S0402]  63.82 38.98 90 top
R25469  *EV@Short_0402  [S0402]  104.33 123.43 180 bottom
R25471  *short_4  [S0402]  76.77 21.58 0 top
R25472  *10K_5%_4  [R0402]  74.97 21.4 0 top
R25473  *Short_0402  [S0402]  76.77 20.56 0 top
R25474  10K_5%_4  [R0402]  91.25 25.77 180 bottom
R25475  10K_5%_4  [R0402]  91.2 25.46 0 top
R25477  10K_1%_2  [R0201]  90.1 27.42 270 bottom
R25479  *Short_0402  [S0402]  101.84 52.92 0 bottom
R25480  *TPC@4.7K_5%_2  [R0201]  95.06 25.26 270 bottom
R25481  *10K_1%_2  [R0201]  93.03 33.51 90 top
R25482  *EV@10K_5%_4  [R0402]  79.39 22.85 180 top
R25483  *Short_0201  [S0201]  211.62 14.21 180 bottom
R25484  *Short_0201  [S0201]  211.75 13.47 180 bottom
R25485  GS_N@0_5%_2  [R0201]  211.75 14.92 180 bottom
R25486  *Short_0402  [S0402]  39.61 116.52 180 bottom
R25487  *EV@0_5%_4  [R0402]  85.13 94.09 0 bottom
R25488  EV@80.6_1%_2  [R0201]  134.81 97.27 180 bottom
R25489  EV@80.6_1%_2  [R0201]  134.17 102.35 180 bottom
R25490  EV@10K_1%_4  [R0402]  87.95 99.05 0 top
R25492  *EV@10K_5%_4  [R0402]  92.57 89.01 90 bottom
R25493  10K_5%_4  [R0402]  65.97 35.65 0 top
R25494  *0_5%_4  [R0402]  65.49 42.76 180 top
R25495  *Short_0402  [S0402]  206.26 27.37 180 top
R25497  33_5%_2  [R0201]  66.79 24.47 0 bottom
R25498  33_5%_2  [R0201]  66.79 25.39 0 bottom
R25499  TPC_N@100K_5%_4  [R0402]  204.33 21.58 270 top
R25500  TPC@100K_5%_4  [R0402]  192.06 33.92 270 bottom
R25501  10K_5%_4  [R0402]  66.74 44.39 0 bottom
R25502  *10K_1%_2  [R0201]  181.72 31.23 90 top
R25503  *Short_0805  [S0805]  41.77 115.23 0 top
R25504  TPC@10K_1%_4  [R0402]  26.22 13.03 90 top
R25511  TPC@0_5%_2  [R0201]  20.89 44.44 180 top
R25512  TPC@0_5%_2  [R0201]  20.89 45.71 180 top
R25513  TPC_N@0_5%_2  [R0201]  21.34 44.44 0 top
R25514  TPC_N@0_5%_2  [R0201]  21.34 45.71 0 top
R25515  TPC_N@0_5%_2  [R0201]  21.34 52.69 180 top
R25516  TPC_N@0_5%_2  [R0201]  21.34 51.55 180 top
R25517  TPC@0_5%_2  [R0201]  20.89 52.69 0 top
R25518  TPC@0_5%_2  [R0201]  20.89 51.55 0 top
R25519  2.2_5%_6  [R0603]  42.86 121.02 0 bottom
R25520  *10K_1%_2  [R0201]  83.37 28.31 270 top
R25521  33_5%_2  [R0201]  56.2 105.04 180 bottom
R25522  33_5%_2  [R0201]  58.05 105.17 90 bottom
RV1  TPC@MESD05N92ULA  [DFN1006-3-1X0_6-0_55H-3P]  11.49 11.29 180 bottom
RV2  TPC@MESD3324PCR  [SON10-2_5X1-5-0_55H]  10.98 16.12 270 bottom
RV3  TPC@MESD3324PCR  [SON10-2_5X1-5-0_55H]  10.98 16.12 90 top
SW1  *T3AL-23S-Q-T/R  [SW-T3AL-23-Q-TR-4P]  167.45 28.87 90 bottom
SW2  *NDT016-G1A-KKKT  [SW-NDT016-G1A-KKKT-4P]  19.1 60.62 180 bottom
SW3  RESET_SW  [SW-TME-532-V-6P]  64.85 100.9 270 bottom
TP1  *  [TP2050]  68.13 85.97 180 bottom
TP3  *  [PAD-TP2050NP-G]  74.48 47.61 0 top
TP4  *  [PAD-TP2050NP-G]  75.88 47.74 0 top
TP5  *  [TP2050]  92.21 26.66 180 bottom
TP6  *  [PAD-TP2050NP-G]  75.75 46.09 0 top
TP7  *  [TP2050]  66.38 39.89 180 bottom
TP9  *  [PAD-TP2050NP-G]  85.56 42.99 0 top
TP10  *  [PAD-TP2050NP-G]  82.26 39.74 0 top
TP11  *  [PAD-TP2050NP-G]  82.74 36.41 0 top
TP12  *  [PAD-TP2050NP-G]  84.64 40.04 0 top
TP14  *  [TP2675]  162.34 29.32 180 top
TP15  *  [TP2675]  160.83 34.34 180 top
TP16  *  [TP2675]  158.99 33.81 180 top
TP17  *  [TP2675]  160.41 29.15 180 top
TP18  *  [TP2675]  157.34 30.97 180 top
TP19  *  [TP2675]  163.13 34.78 180 top
TP20  *  [PAD-TP2050NP-G]  81.09 36.31 0 top
TP21  *  [PAD-TP2050NP-G]  88.12 36.54 0 top
TP22  *PAD  [TP2050]  101.99 72.5 180 bottom
TP23  *PAD  [PAD-TP2050NP-G]  97.22 69.18 0 top
TP24  *PAD  [TP2050]  101.15 71.28 180 bottom
TP25  *PAD  [PAD-TP2050NP-G]  99.25 68.97 0 top
TP26  *PAD  [PAD-TP2050NP-G]  104.41 67.3 0 top
TP27  *PAD  [PAD-TP2050NP-G]  95.21 73.72 0 top
TP28  *PAD  [PAD-TP2050NP-G]  94.42 71.79 0 top
TP29  *PAD  [TP2050]  100.19 74.13 0 top
TP30  *PAD  [PAD-TP2050NP-G]  100.34 69.66 0 top
TP31  *PAD  [PAD-TP2050NP-G]  100.14 70.98 0 top
TP32  *PAD  [TP2050]  102.8 75.02 0 top
TP33  *PAD  [PAD-TP2050NP-G]  98.36 72.71 0 top
TP34  *PAD  [TP2050]  100.21 76.06 0 top
TP35  *PAD  [PAD-TP2050NP-G]  99.02 71.61 0 top
TP36  *PAD  [TP2050]  98.49 74 0 top
TP37  *PAD  [PAD-TP2050NP-G]  96.68 71.84 0 top
TP38  *PAD  [TP2050]  97.34 75.63 0 top
TP39  *PAD  [TP2050]  100.04 72.86 0 top
TP40  *PAD  [TP2050]  104.89 74.56 0 top
TP41  *PAD  [PAD-TP2050NP-G]  96.84 70.55 0 top
TP42  *PAD  [TP2050]  98.94 76.29 0 top
TP43  *PAD  [TP2050]  105.68 67.02 0 top
TP44  *PAD  [PAD-TP2050NP-G]  97.01 73.09 0 top
TP45  *PAD  [TP2050]  102.68 58.53 180 bottom
TP46  *PAD  [TP2050]  99.22 75.04 0 top
TP47  *PAD  [TP2050]  102.65 57.26 180 bottom
TP48  *PAD  [TP2050]  97.24 74.36 0 top
TP50  *PAD  [PAD-TP2050NP-G]  94.32 69 0 top
TP52  *PAD  [PAD-TP2050NP-G]  98.11 70.65 0 top
TP54  *PAD  [TP2050]  114.29 21.98 0 top
TP55  *PAD  [TP2050]  112.33 22.54 0 top
TP65  *  [TP2050]  86.29 92.19 0 top
TP66  *  [TP2050]  90.36 91.68 0 top
TP67  *  [TP2050]  103.69 96 0 top
TP68  *  [TP2050]  102.2 96.63 0 top
TP69  *  [TP2050]  107 89.14 0 top
TP70  *  [TP2050]  95.72 118.35 180 bottom
TP71  *  [TP2050]  94.45 118.35 180 bottom
TP72  *  [TP2050]  97.01 118.35 180 bottom
TP73  *  [TP2050]  98.61 118.35 180 bottom
TP74  *  [TP2050]  46.65 109.98 180 top
TP75  *  [TP2050]  47.52 111.38 180 top
TP76  *  [TP2050]  47.83 109.42 180 top
TP77  *PAD  [TP2050]  11.24 12.81 0 top
TP78  *PAD  [TP2050]  9.97 20.05 180 bottom
TP81  *PAD  [TP2050]  19.18 5.79 0 top
TP2090  *TP  [TP2050]  187.56 10.5 0 top
TP2092  *PAD  [TP2050]  37.53 4.3 0 top
TP9000  *TP  [TP2050]  70.55 113.91 0 top
TP9001  *TP  [TP2050]  136.97 33.64 0 top
TP9011  *  [TP2050]  78.55 40.88 0 top
TP9012  *  [TP2050]  77.28 40.85 0 top
TP9018  *  [PAD-TP2050NP-G]  75.75 42.91 0 top
TP9019  *TP  [TP2050]  186.8 31.23 90 top
TP9021  *TP  [TP2050]  181.44 27.29 0 top
TP9023  *  [TP2050]  209.71 26.96 0 top
TP9024  *  [TP2050]  209.52 30.48 0 top
TP9025  *  [TP2050]  93.41 37.07 0 top
TP9026  *  [TP2050]  62.5 30.97 0 top
TP9027  *  [PAD-TP2050NP-G]  75.37 44.44 0 top
TP9029  *PAD  [TP2050]  192.04 32.4 180 bottom
TP9030  *  [TP2050]  90.1 111.87 180 bottom
TP9031  *  [TP2050]  91.12 106.92 180 bottom
TP9032  *  [TP2050]  90.1 110.6 180 bottom
TP9033  *  [TP2050]  91.12 105.4 180 bottom
TP9035  *TP  [TP2050]  200.37 23.23 0 top
TP9037  *TP  [TP2050]  200.8 24.98 0 top
TP9038  *TP  [TP2050]  181.77 20.64 0 top
TP9039  *TP  [TP2050]  181.09 16.6 0 top
TP9040  *TP  [TP2050]  189.93 12.64 0 top
TP9041  *TP  [TP2050]  181.77 22.49 0 top
TP9042  *TP  [PAD-TP2050NP-G]  70.17 39.64 0 top
TP9043  *TP  [PAD-TP2050NP-G]  70.67 38.21 0 top
TP9044  *TP  [PAD-TP2050NP-G]  69.28 38.72 0 top
U1  WHL_U_43E_IL_IP_DDR4  [BGA1528-INTEL-WHL-U]  86.06 57 270 bottom
U2  W25Q64FVSSIQ  [SOIC8-7_9-1_27-2_16H]  161.35 29.83 180 bottom
U3  *APL3512ABI-TRG  [SOT23-5-2_8-95-5P-G708]  63.23 26.02 180 bottom
U4  DDR4_96P  [BGA96-MICRON-MT41J64M16JT-187EG]  40.27 41.48 270 top
U5  DDR4_96P  [BGA96-MICRON-MT41J64M16JT-187EG]  40.27 54.63 270 top
U6  DDR4_96P  [BGA96-MICRON-MT41J64M16JT-187EG]  40.27 89.36 270 top
U7  DDR4_96P  [BGA96-MICRON-MT41J64M16JT-187EG]  40.27 76.06 270 top
U8  EV@N17S-G1-A1  [BGA595-NVIDIA-N13P-GV2-S-A2]  105.03 103.73 90 bottom
U9  EV@NL17SZ08DFT2G  [SOT353-1-2_125-65-5P]  97.47 123.68 180 bottom
U11  EV@NL17SZ32DFT2G  [SOT353-2_1-65-5P]  101.03 121.14 270 bottom
U14  TPC@SLGC55544VTR  [QFN16-3X3-5-17P-TPS2546RTER]  20.13 48.63 0 top
U15  G524B2T11U  [SOT23-5-2_8-95-5P-G708]  19.49 44.18 180 bottom
U16  USB30_ESD_AZ1065-06F.R7G  [ESD10-4_1X2-8-11P]  19.24 55.23 90 top
U17  USB30_ESD_AZ1065-06F.R7G  [ESD10-4_1X2-8-11P]  18.73 34.78 90 top
U18  G524B2T11U  [SOT23-5-2_8-95-5P-G708]  206.51 21.27 0 bottom
U19  APL3512ABI-TRG  [SOT23-5-2_8-95-5P-G708]  80.96 98.16 180 bottom
U20  ALC255-CG  [QFN48-6X6-4-49P-ALC280]  204.66 32.63 180 bottom
U23  HDMI_R@PTN3366BS  [QFN32-5X5-5-37P-0_85H]  21.27 78.47 180 top
U24  RTL8111HSH-CG  [QFN32-4X4-4-33P-0_9H]  44.64 105.4 270 top
U25  NS892407  [TRF-N1010G-25P]  32.4 107.58 180 bottom
U32  GS@LIS3DHTR  [LGA16-3X3-5]  58.74 21.96 0 top
U33  TPM@NPCT750AAAYX  [QFN32-5X5-5-33P-0_85H]  125.69 20.46 90 top
U35  CNV@NL17SZ08DFT2G  [SOT353-1-2_125-65-5P]  146.47 27.32 270 top
U36  CNV@NL17SZ08DFT2G  [SOT353-1-2_125-65-5P]  146.44 20.64 270 top
U37  IT8987E/CX  [LQFP128-16X16-4-1_6H]  191.05 21.98 270 top
U42  HDD_R@SN75LVCP601RTJR  [PWQFN20-4X4-5-26P-0_8H]  210.88 16.37 180 top
U6502  TPC@PI2EQX632EXUBE_TQFN18  [QFN18-2X2-4-19P-0_4H-SMT]  18.1 22.34 270 bottom
U6503  TPC@TPS25810RVCR(QFN)  [QFN20-4X3-5-27P]  24.7 15.61 270 bottom
U6504  *NL17SZ08DFT2G  [SOT353-1-2_125-65-5P]  88.83 23.68 180 bottom
VC2  *TVM0G5R5M220R  [C0402]  14.92 85.97 0 top
VRAM1  EV@K4G80325FB-HC28_GDDR5_170P  [BGA170-HYNIX-H5GQ1H24MJR]  133.41 88.6 180 bottom
VRAM2  EV@K4G80325FB-HC28_GDDR5_170P  [BGA170-HYNIX-H5GQ1H24MJR]  133.41 111 0 bottom
Y1  32.768KHZ/20ppm  [XTL-3_2X1_5-2_5-SMT]  78.98 29.83 0 bottom
Y2  24MHZ/20ppm  [XTL-2X1_6-1_35X1_05]  100.14 27.06 0 bottom
Y3  EV@27MHZ/10ppm  [XTL-3_2X2_5-2_2X1_7-0_8H]  100.77 86.85 0 bottom
Y4  25MHZ/30ppm  [XTL-2_05X1_65-1_4X1_1-0_6H]  45.27 112.89 180 top

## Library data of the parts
C1 C2 C5-C9 C11-C28 C30-C119 C122-C195 C200-C206 C208 C209 C212-C227 C229-C244 C246 C247 C249-C280 C347-C360 C362-C384 C386-C389 C391-C403 C406-C433 C438-C462 C471-C506 C508-C533 C536 C537 C542-C548 C550 C552-C562 C566 C567 C613 C614 C616 C618 C619 C628 C631-C644 C646 C664 C665 C675-C677 C680-C686 C691 C692 C695-C699 C706-C709 C711 C713-C733 C735 C770-C772 C779 C785 C786 C788-C795 C800-C802 C804 C841 C842 C847-C854 C1189 C1190 C1211 C1214 C1217 C1675-C1693 C2609-C2612 C2616 C6550-C6557 C6565 C6569 C6570 C6573-C6575 C6577 C6578 C6586-C6603 C6606-C6608 C6615 C6617-C6620 C6622-C6624 C6626 C20000 EC1-EC3 EC5 EC6 EC11-EC13 VC2 = CAP_NON-POL_BGM
C3 C228 C248 C281-C346 C463 C464 C563-C565 C568 C569 C572-C578 C580 C581 C583-C599 C601-C604 C645 C734 C736 C737 C740-C745 C749 C750 C752 C753 C773-C778 C780-C784 C805 C843-C846 C1044 C1208 C1210 C2374 C2607 C6502-C6505 C6544-C6549 C6559 C6560 C6562-C6564 C6566 C6568 C6571 C6572 C6580 C6582-C6584 C6604 C6605 C6609 C6610 C6616 C6625 C20001 C20002 EC9 EC10 EC6500 = CAP NON-POL_BGM
C29 C385 = CAP_POL_BGM
C245 = CAP_NON-POL_BGM: tolerance: CH6471M9900
C6581 = CAP POL_BGM
C6612-C6614 = C-0603
CN1 = Header_2P_BGM
CN2 CN3 = HEADER 4_0
CN8 = RJ45_8P_4fix_V3_BGM
CN10 = TYPEC_2
CN13 CN36 = FFCFPC_4P_BGM
CN14 CN33 = FFCFPC_8P_BGM
CN15 = FFCFPC_18P_BGM
CN16 = NGFF_79P_MKEY_NAME_BGM
CN17 = NGFF_79P_EKEY_NAME_BGM
CN18 CN19 = FFCFPC_28P_BGM
CN24 = FFCFPC_4P_2F_BGM
CN29 CN35 = FFCFPC_40P_BGM
CN37 = HDMI_19P_10444-19001_BGM
CN38 = HEADER_4P_50208-00401-V02_BGM
D1 D4 D12 D13 D20 D21 D51 D60-D64 D2016 = Schottky_DIODE_BGM
D3 D11 D6543 = DIODE_BGM
D14 = BAT54A_BGM
D16-D19 D65 = Varistor_BGM
D22 D33 D34 D50 D13081-D13092 EC7 EC8 = TVS_DIODE_BGM
D72 = DIODE SCHOTTKY_1
D6541 = ZENER_DIODE_BGM
D6542 = ZENER1 DIODE
FAN3 = Header_4P_BGM
HD1 = FFCFPC_12P_V1_BGM
HE1 = HALL_IC_3P_BGM
HOLE2-HOLE6 HOLE10 HOLE12-HOLE18 HOLE21-HOLE24 = 3x2_1.1
HOLE7-HOLE9 HOLE11 HOLE19 HOLE20 = 3x2_0.1
J9007 = OPEN
JDIM1 = DDR4_DIMM_260P_BGM
L1-L8 L11-L13 L15 L16 L23 L24 L28-L30 = BEAD_BGM
PC1 PC225 PC6028 PC6029 PC6056 PC6057 PC9062 PC9063 PC9089 = CAP_NON-POL_BGM: tolerance: CH21006JB10
PC2 PC15 = CAP_NON-POL_BGM: tolerance: CH34706K912
PC3 PC4 PC6 PC235 PC9079 = CAP_NON-POL_BGM: tolerance: CH4104K1B00
PC5 PC12 PC14 PC167 = CAP_NON-POL_BGM: tolerance: CH4106K1B01
PC7 PC13 PC51 PC152 PC165 PC172 PC218 PC292 PC300 PC6002 PC6034 PC7035 PC7046 PC7054 PC7064 PC7069 PC7078 PC7085 PC7096 PC9006 PC9012 PC9019 PC9024 PC9077 = CAP_NON-POL_BGM: tolerance: CH22206KB16
PC8 PC17 PC221 PC572 PC9071 PC9074 = CAP_NON-POL_BGM: tolerance: CH31006KB18
PC9 PC9000 = CAP_NON-POL_BGM: tolerance: CH5222K9B06
PC10 PC11 = CAP_NON-POL_BGM: tolerance: CH04706JB01
PC16 = CAP_NON-POL_BGM: tolerance: CH4474K1907
PC18 PC20 PC37 PC168 PC9028 = CAP_NON-POL_BGM: tolerance: CH11006JB00
PC19 PC82 PC6006 PC6038 PC9088 = CAP_NON-POL_BGM: tolerance: CH16806J911
PC25 PC35 PC36 = CAP_NON-POL_BGM: tolerance: CH4106K9B01
PC81 PC290 PC301 PC6000 PC6001 PC6003 PC6030 PC6031 PC6035 PC7034 PC7038 PC7053 PC7055 PC7068 PC7070 PC7084 PC7086 PC7099 PC9003 PC9018 PC9076 = CAP_NON-POL_BGM: tolerance: CH4104K9B03
PC83 PC219 PC220 PC222 PC224 PC227 PC230 PC231 PC236 PC562 PC563 PC6008-PC6012 PC6014 PC6044-PC6049 PC9080-PC9086 PC9098 = CAP_NON-POL_BGM: tolerance: CH6221M9900
PC162 PC7044 PC7045 PC7062 PC7094 PC7095 PC9010 PC9011 PC9021 = CAP_POL_BGM: tolerance: CH733RY8802
PC164 PC166 = CAP_NON-POL_BGM: tolerance: CH6224M9A00
PC170 PC217 PC288 PC289 PC6004 PC6005 PC6032 PC6033 PC7031-PC7033 PC7037 PC7049-PC7052 PC7066 PC7067 PC7080-PC7083 PC9001 PC9002 PC9005 PC9015-PC9017 PC9078 = CAP_NON-POL_BGM: tolerance: CH6104K9A00
PC185 PC6015 PC6016 PC6036 PC6037 PC9053 PC9054 = CAP_NON-POL_BGM: tolerance: CH5104K9B01
PC188 PC423 PC561 PC581 PC7003 PC7005 PC7006 PC7025 PC7027 PC7029 PC7030 PC9093 PC9094 = CAP_NON-POL_BGM: tolerance: CH4101K9E01
PC228 PC232 = CAP_NON-POL_BGM: tolerance: CH3471K9E03
PC229 PC234 PC299 PC302 PC304 PC6018 PC6021 PC6040 PC6043 PC6230 PC9055 PC9058 PC9066-PC9068 PC9075 = CAP_NON-POL_BGM: tolerance: CH6101M9905
PC233 PC276 PC280 PC283 PC293 PC756 PC6007 PC6013 PC6017 PC6019 PC6020 PC6025-PC6027 PC6039 PC6041 PC6042 PC6050-PC6053 PC6055 PC6228 PC6231 PC7039 PC7057 PC7087 PC9023 PC9056 PC9057 PC9059 PC9060 PC9065 PC9069 PC9072 PC9073 PC9087 = CAP_NON-POL_BGM: tolerance: CH4103K1B08
PC242 = CAP_NON-POL_BGM: tolerance: CH5471M9B00
PC267 = CAP_NON-POL_BGM: tolerance: CH11506JB08
PC268 PC285 PC7063 PC7102 PC7104 PC7106 = CAP_NON-POL_BGM: tolerance: CH5101K9B01
PC294-PC297 PC305 PC306 PC7040-PC7043 PC7058-PC7061 PC7072-PC7077 PC7088-PC7093 PC9009 PC9022 = CAP_NON-POL_BGM: tolerance: CH6221M9A00
PC298 = CAP_NON-POL_BGM: tolerance: CH33302KB12
PC551 = CAP_NON-POL_BGM: tolerance: CH22206K917
PC571 PC9092 PC9095 PC9096 = CAP_NON-POL_BGM: tolerance: CH6101M9B02
PC574 PC9097 = CAP_NON-POL_BGM: tolerance: CH02206JB08
PC6022 PC6058 = CAP_NON-POL_BGM: tolerance: CH5102K9B06
PC6023 = CAP_NON-POL_BGM: tolerance: CH5471K9B00
PC6024 PC6059 = CAP_NON-POL_BGM: tolerance: CH01006JB08
PC6054 = CAP_NON-POL_BGM: tolerance: CH5472K9901
PC6229 PC7047 PC7065 PC7079 PC7097 = CAP_NON-POL_BGM: tolerance: CH4471K9B03
PC7000 = CAP NON-POL_BGM: tolerance: CH4224K1B01
PC7001 = CAP NON-POL_BGM: tolerance: CH21006JB10
PC7004 = CAP_NON-POL_BGM: tolerance: CH4471K9E00
PC7007-PC7009 PC7013-PC7015 PC7019 PC7022 PC7024 = CAP NON-POL_BGM: tolerance: CH11006JB00
PC7010 = CAP_NON-POL_BGM: tolerance: CH1333K1E01
PC7011 PC7017 = CAP NON-POL_BGM: tolerance: CH08206JB04
PC7012 PC7018 PC7021 PC7023 = CAP NON-POL_BGM: tolerance: CH06806JB01
PC7016 = CAP NON-POL_BGM: tolerance: CH12706KB12
PC7020 = CAP_NON-POL_BGM: tolerance: CH1566K1B09
PC7026 = CAP NON-POL_BGM: tolerance: CH5471M9B00
PC7036 PC9007 = CAP_POL_BGM: tolerance: CH6154M8600
PC7056 PC7101 PC7103 PC7105 PC9008 PC9020 = CAP_NON-POL_BGM: tolerance: CH4224K1900
PC7100 = CAP_NON-POL_BGM: tolerance: CH2104K1B00
PC9004 = CAP_NON-POL_BGM: tolerance: CH5104K1900
PC9013 PC9014 PC9090 = CAP_NON-POL_BGM: tolerance: CH4222K9B04
PC9025 = CAP_NON-POL_BGM: tolerance: CH24704KB19
PC9026 = CAP_NON-POL_BGM: tolerance: CH21506KB14
PC9027 PC9029 PC9030 = CAP_NON-POL_BGM: tolerance: CH05606JB01
PC9064 = CAP_NON-POL_BGM: tolerance: CH18206KB11
PC9091 = CAP_NON-POL_BGM: tolerance: CH3101K1E09
PD2 = ZENER_DIODE_BGM: tolerance: BCAFJ20AZ00
PD3 PD4 = ZENER_DIODE_BGM: tolerance: BDPDZ56BZ07
PD9000 = Schottky_DIODE_BGM: tolerance: BCRB500VZ29
PD9001 = DIODE_BGM: tolerance: BC1SS355Z21
PJ1 = HEADER_8P_2F_BGM: tolerance: DFHD08MR201
PJ2 = DCJACK_30706-00042-001_BGM: tolerance: DFPJ03MR143
PJ3005 PJ3008 PJ6001 PJ6003 PJ9002 PJ9003 PJ9005 PR4-PR6 PR8 PR11 PR17 PR19 PR25 PR26 PR30 PR32 PR210 PR262 PR265 PR267 PR272-PR274 PR276 PR284 PR566 PR2060 PR3022 PR6002 PR6004 PR6005 PR6013 PR6015-PR6017 PR6020 PR6022 PR6023 PR6025 PR6027 PR6028 PR6417 PR7012 PR7020 PR7025 PR7039 PR7044 PR7046 PR7051 PR7053 PR7058 PR7062 PR7067 PR7077 PR7079 PR7102 PR7105 PR7107 PR7109 PR7111 PR7113 PR7115 PR9008 PR9015-PR9017 PR9028 PR9029 PR9034 PR9067-PR9070 PR9072 PR9078 PR9079 PR9085 PR9090 PR9093 PR9098 PR9244 PR9245 PR9248 PR9249 PR9256 PR9258 PR9267 PR9269 PR9271 PR9273 = SHORTPAD_V01_BGM
PJ7001 = SHORTPAD_V01_BGM: tolerance: TMPSHT00006
PL5 = INDUCTOR_BGM: tolerance: CV-6845MZ05
